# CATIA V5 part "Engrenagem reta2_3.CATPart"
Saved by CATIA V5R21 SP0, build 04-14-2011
Part number: Engrenagem reta2_3
Definition: Engrenagem reta2_3
Nomenclature: Engrenagem reta27
Source: Unknown
Bounding box of the stored display mesh (mm): x -2.788 to 2.788, y -2.787 to 2.787, z 0 to 0.5
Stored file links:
  C:\Users\beatr\OneDrive\Documents\UNB\2026_1\Pi1\Componentes eletronicos\Engrenagem reta2_3.CATPart
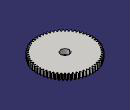
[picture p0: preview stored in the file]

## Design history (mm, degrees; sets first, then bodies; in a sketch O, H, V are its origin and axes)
Body1 "Solid1" (main body)
  Solid1: solid without history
